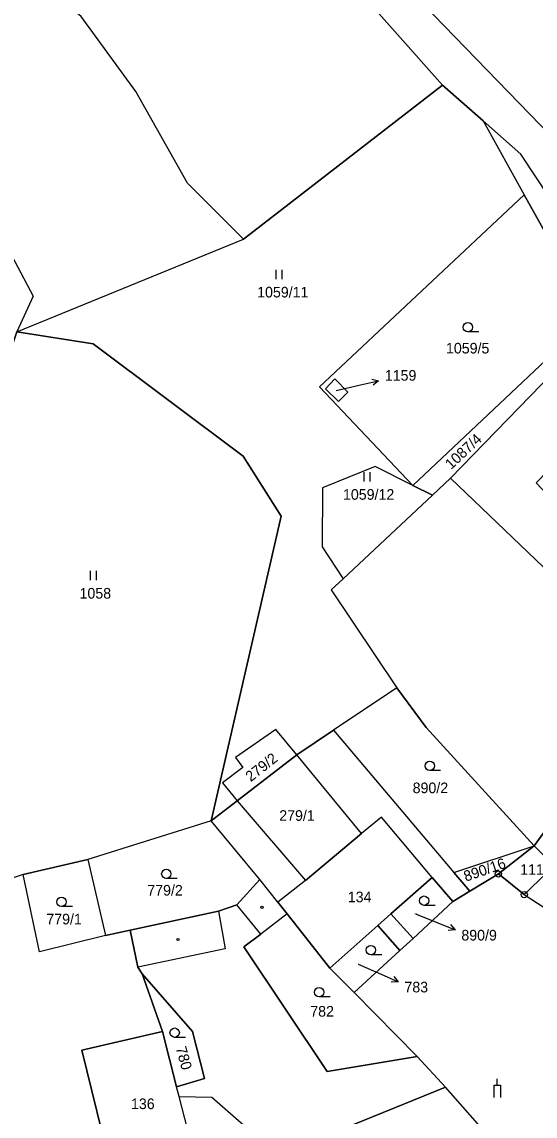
# Model space of a CAD drawing. Extents: x -654083 to -650132, y -1099819 to -1096699.
# Drawn here: x -653142.9 to -653060.7, y -1098197.5 to -1098022.1 of the extents above; entities that cross this region are included whole.
import ezdxf

# ---------------------------------------------------------------- set-up
doc = ezdxf.new("R2010")
doc.units = 0
for name, color, linetype in [('Geodetické body', 7, 'Continuous'), ('Hranice - vnitř_ kresba', 7, 'Continuous'), ('Obvody jako plochy', 7, 'Continuous'), ('Ostatní mapové značky 2', 7, 'Continuous'), ('Parcelní čísla', 7, 'Continuous'), ('Prvky pro prodl_ par_ č_', 7, 'Continuous'), ('Značky kultur', 7, 'Continuous'), ('Značky na budově ne v SPI', 7, 'Continuous')]:
    doc.layers.add(name, color=color, linetype=linetype)

msp = doc.modelspace()

# ---------------------------------------------------------------- linework, layer by layer
at = {"layer": 'Geodetické body'}
for centre, radius in [((-653066.55, -1098158.69), 0.5), ((-653066.55, -1098158.69), 0.001), ((-653062.42, -1098161.99), 0.5), ((-653062.42, -1098161.99), 0.001)]:
    msp.add_circle(centre, radius, dxfattribs=at)
at = {"layer": 'Hranice - vnitř_ kresba'}
for p, q in [((-653085.29, -1098149.58), (-653088.46, -1098152.23)), ((-653077.16, -1098159.23), (-653085.29, -1098149.58)), ((-653101.87, -1098163.22), (-653104.75, -1098159.59)), ((-653097.48, -1098159.75), (-653101.87, -1098163.22)), ((-653100.38, -1098165.1), (-653101.87, -1098163.22)), ((-653111.39, -1098164.65), (-653110.33, -1098170.7)), ((-653085.86, -1098166.94), (-653083.77, -1098165.07)), ((-653110.33, -1098170.7), (-653124.29, -1098173.63)), ((-653117.7, -1098194.34), (-653118.1, -1098192.78))]:
    msp.add_line(p, q, dxfattribs=at)
at = {"layer": 'Obvody jako plochy'}
for points in [[(-653150.23, -1097911.49), (-653071.26, -1097984.33), (-653053.39, -1098005.53), (-653037.15, -1098027.99), (-653053.78, -1098046.95), (-653058.1, -1098040.43), (-653190.24, -1097904.12), (-653233.05, -1097864.49), (-653269.43, -1097824.84), (-653263.01, -1097791.35), (-653215.43, -1097850.17)], [(-653159.78, -1097992.82), (-653143.05, -1097977.01), (-653174.94, -1097944.83), (-653220.04, -1097975.33), (-653208.83, -1097985.73), (-653199.6, -1098001.2), (-653194.63, -1098009.53), (-653169.63, -1098032.13), (-653152.81, -1098047.34), (-653149.48, -1098050.35), (-653141.08, -1098066.12), (-653143.72, -1098071.82), (-653107.4, -1098056.94), (-653116.37, -1098047.99), (-653124.61, -1098033.31), (-653133.37, -1098021.26), (-653147.28, -1098010.02)], [(-653075.5, -1098032.29), (-653107.4, -1098056.94), (-653116.37, -1098047.99), (-653124.61, -1098033.31), (-653133.37, -1098021.26), (-653147.28, -1098010.02), (-653159.78, -1097992.82), (-653143.05, -1097977.01), (-653139.93, -1097974.11), (-653120.37, -1097998.7), (-653111.98, -1097991.16)], [(-653062.45, -1098049.88), (-653095.19, -1098080.64), (-653080.27, -1098096.44), (-653086.3, -1098093.39), (-653094.72, -1098096.79), (-653094.8, -1098106.24), (-653091.4, -1098111.38), (-653093.32, -1098113.17), (-653082.85, -1098128.85), (-653092.97, -1098135.64), (-653098.84, -1098139.62), (-653102.23, -1098135.55), (-653108.65, -1098140.04), (-653107.47, -1098141.62), (-653110.73, -1098144.07), (-653108.39, -1098146.98), (-653112.54, -1098150.18), (-653101.36, -1098101.34), (-653107.45, -1098091.76), (-653131.48, -1098073.76), (-653143.72, -1098071.82), (-653107.4, -1098056.94), (-653075.5, -1098032.29), (-653069, -1098038.01)], [(-653052.35, -1098072.7), (-653049.59, -1098069.85), (-653056.05, -1098053.74), (-653062.97, -1098043.33), (-653069, -1098038.01), (-653062.45, -1098049.88), (-653051.51, -1098069.36), (-653080.27, -1098096.44), (-653077.11, -1098098), (-653074.21, -1098095.28)], [(-653153.06, -1098099.55), (-653163, -1098138.19), (-653175.95, -1098136.58), (-653183.53, -1098124.46), (-653202.43, -1098112.89), (-653152.81, -1098047.34), (-653149.48, -1098050.35), (-653141.08, -1098066.12), (-653143.72, -1098071.82)], [(-653080.27, -1098096.44), (-653051.51, -1098069.36), (-653062.45, -1098049.88), (-653095.19, -1098080.64)], [(-653037.53, -1098097.49), (-653052.73, -1098111.83), (-653053.71, -1098110.99), (-653055.61, -1098113.11), (-653074.21, -1098095.28), (-653052.35, -1098072.7), (-653049.59, -1098069.85), (-653045.09, -1098080.16)], [(-653143.72, -1098071.82), (-653131.48, -1098073.76), (-653107.45, -1098091.76), (-653101.36, -1098101.34), (-653112.54, -1098150.18), (-653132.3, -1098156.38), (-653142.69, -1098158.75), (-653160.81, -1098164.87), (-653163, -1098138.19), (-653153.06, -1098099.55)], [(-653055.61, -1098113.11), (-653074.21, -1098095.28), (-653052.35, -1098072.7), (-653045.09, -1098080.16), (-653060.52, -1098096), (-653050.13, -1098107.02), (-653053.71, -1098110.99)], [(-653090.65, -1098081.46), (-653092.19, -1098082.97), (-653094.27, -1098080.92), (-653092.76, -1098079.32)], [(-653092.76, -1098079.32), (-653090.65, -1098081.46), (-653092.19, -1098082.97), (-653094.27, -1098080.92)], [(-653091.4, -1098111.38), (-653077.11, -1098098), (-653080.27, -1098096.44), (-653086.3, -1098093.39), (-653094.72, -1098096.79), (-653094.8, -1098106.24)], [(-653053.71, -1098110.99), (-653055.61, -1098113.11), (-653074.21, -1098095.28), (-653077.11, -1098098), (-653091.4, -1098111.38), (-653093.32, -1098113.17), (-653082.85, -1098128.85), (-653078.13, -1098135.23), (-653060.83, -1098154.16), (-653049.44, -1098138.5), (-653045.05, -1098140.86), (-653035.15, -1098125.51), (-653030.07, -1098117.11), (-653027.32, -1098113), (-653031.29, -1098104.31), (-653037.53, -1098097.49), (-653052.73, -1098111.83)], [(-653060.83, -1098154.16), (-653078.13, -1098135.23), (-653082.85, -1098128.85), (-653092.97, -1098135.64), (-653073.71, -1098158.44)], [(-653080.21, -1098169.03), (-653082.36, -1098170.94), (-653085.86, -1098166.94), (-653093.57, -1098173.76), (-653100.38, -1098165.1), (-653104.62, -1098168.32), (-653108.47, -1098163.66), (-653104.75, -1098159.59), (-653112.54, -1098150.18), (-653108.39, -1098146.98), (-653097.48, -1098159.75), (-653088.46, -1098152.23), (-653098.84, -1098139.62), (-653092.97, -1098135.64), (-653073.71, -1098158.44), (-653071.14, -1098161.44), (-653073.84, -1098163.12), (-653077.16, -1098159.23), (-653083.77, -1098165.07)], [(-653098.84, -1098139.62), (-653102.23, -1098135.55), (-653108.65, -1098140.04), (-653107.47, -1098141.62), (-653110.73, -1098144.07), (-653108.39, -1098146.98)], [(-653108.65, -1098140.04), (-653107.47, -1098141.62), (-653110.73, -1098144.07), (-653108.39, -1098146.98), (-653098.84, -1098139.62), (-653102.23, -1098135.55)], [(-653097.48, -1098159.75), (-653088.46, -1098152.23), (-653098.84, -1098139.62), (-653108.39, -1098146.98)], [(-653108.39, -1098146.98), (-653097.48, -1098159.75), (-653088.46, -1098152.23), (-653098.84, -1098139.62)], [(-653053.99, -1098157.86), (-653052.76, -1098155.51), (-653045.05, -1098140.86), (-653049.44, -1098138.5), (-653060.83, -1098154.16), (-653057.61, -1098157.36), (-653055.14, -1098159.81)], [(-653085.86, -1098166.94), (-653083.77, -1098165.07), (-653077.16, -1098159.23), (-653085.29, -1098149.58), (-653088.46, -1098152.23), (-653097.48, -1098159.75), (-653101.87, -1098163.22), (-653100.38, -1098165.1), (-653093.57, -1098173.76)], [(-653108.47, -1098163.66), (-653104.75, -1098159.59), (-653112.54, -1098150.18), (-653132.3, -1098156.38), (-653129.48, -1098168.54), (-653125.55, -1098167.69), (-653111.39, -1098164.65)], [(-653066.55, -1098158.69), (-653071.14, -1098161.44), (-653073.71, -1098158.44), (-653060.83, -1098154.16)], [(-653062.42, -1098161.99), (-653066.55, -1098158.69), (-653060.83, -1098154.16), (-653057.61, -1098157.36)], [(-653132.3, -1098156.38), (-653129.48, -1098168.54), (-653140.06, -1098171.16), (-653142.69, -1098158.75)], [(-653140.06, -1098171.16), (-653142.69, -1098158.75), (-653160.81, -1098164.87), (-653165.45, -1098167.24), (-653166.29, -1098184.39), (-653163.28, -1098198.26), (-653156.38, -1098205.89), (-653150.52, -1098224.84), (-653141.18, -1098219.21), (-653127.65, -1098213.56), (-653113.09, -1098212.74), (-653113.57, -1098209.43), (-653115.41, -1098203.29), (-653128.45, -1098206.67), (-653133.29, -1098186.91), (-653120.36, -1098183.92), (-653123.61, -1098174.68), (-653124.29, -1098173.63), (-653125.55, -1098167.69), (-653129.48, -1098168.54)], [(-653055.14, -1098159.81), (-653057.61, -1098157.36), (-653062.42, -1098161.99), (-653051.6, -1098169.04), (-653046.15, -1098163.95), (-653053.32, -1098158.38), (-653053.99, -1098157.86)], [(-653073.84, -1098163.12), (-653080.21, -1098169.03), (-653083.77, -1098165.07), (-653077.16, -1098159.23)], [(-653079.59, -1098187.95), (-653094, -1098190.37), (-653107.31, -1098170.36), (-653104.62, -1098168.32), (-653108.47, -1098163.66), (-653111.39, -1098164.65), (-653125.55, -1098167.69), (-653124.29, -1098173.63), (-653123.61, -1098174.68), (-653115.58, -1098183.94), (-653113.62, -1098191.47), (-653118.1, -1098192.78), (-653120.36, -1098183.92), (-653133.29, -1098186.91), (-653128.45, -1098206.67), (-653115.41, -1098203.29), (-653117.7, -1098194.34), (-653112.47, -1098194.44), (-653101.85, -1098203.76), (-653075.01, -1098192.86)], [(-653093.57, -1098173.76), (-653100.38, -1098165.1), (-653104.62, -1098168.32), (-653107.31, -1098170.36), (-653094, -1098190.37), (-653079.59, -1098187.95), (-653089.68, -1098177.7)], [(-653082.36, -1098170.94), (-653089.68, -1098177.7), (-653093.57, -1098173.76), (-653085.86, -1098166.94)], [(-653115.58, -1098183.94), (-653123.61, -1098174.68), (-653120.36, -1098183.92), (-653118.1, -1098192.78), (-653113.62, -1098191.47)], [(-653128.45, -1098206.67), (-653115.41, -1098203.29), (-653117.7, -1098194.34), (-653118.1, -1098192.78), (-653120.36, -1098183.92), (-653133.29, -1098186.91)], [(-653054.02, -1098216.68), (-653075.01, -1098192.86), (-653101.85, -1098203.76), (-653113.57, -1098209.43), (-653113.09, -1098212.74), (-653105.4, -1098235.64), (-653102.24, -1098235.17), (-653085.2, -1098247.42), (-653065.64, -1098241.83)], [(-653101.85, -1098203.76), (-653113.57, -1098209.43), (-653115.41, -1098203.29), (-653117.7, -1098194.34), (-653112.47, -1098194.44)]]:
    msp.add_lwpolyline(points, close=True, dxfattribs=at)
for points in [[(-653190.24, -1097904.12), (-653058.1, -1098040.43), (-653053.78, -1098046.95), (-653049.22, -1098053.83), (-653045.67, -1098067.27), (-653044.29, -1098069.82), (-653034.66, -1098087.65), (-653023.18, -1098108.58), (-653022.38, -1098110.19), (-653027.32, -1098113), (-653031.29, -1098104.31), (-653037.53, -1098097.49), (-653045.09, -1098080.16), (-653049.59, -1098069.85), (-653056.05, -1098053.74), (-653062.97, -1098043.33), (-653069, -1098038.01), (-653075.5, -1098032.29), (-653111.98, -1097991.16), (-653194.36, -1097906.79)], [(-653054.02, -1098216.68), (-653075.01, -1098192.86), (-653079.59, -1098187.95), (-653089.68, -1098177.7), (-653082.36, -1098170.94), (-653080.21, -1098169.03), (-653073.84, -1098163.12), (-653071.14, -1098161.44), (-653066.55, -1098158.69), (-653062.42, -1098161.99), (-653051.6, -1098169.04)]]:
    msp.add_lwpolyline(points, dxfattribs=at)
at = {"layer": 'Ostatní mapové značky 2'}
msp.add_line((-653066.74, -1098192.52), (-653066.74, -1098191.52), dxfattribs=at)
msp.add_lwpolyline([(-653067.24, -1098194.52), (-653067.24, -1098192.52), (-653066.24, -1098192.52), (-653066.24, -1098194.52)], dxfattribs=at)
at = {"layer": 'Prvky pro prodl_ par_ č_'}
for p, q in [((-653088.67, -1098080.32), (-653085.75, -1098079.64)), ((-653092.53, -1098081.23), (-653088.67, -1098080.32)), ((-653079.84, -1098165.07), (-653076.27, -1098166.52)), ((-653076.27, -1098166.52), (-653073.49, -1098167.65)), ((-653089.01, -1098173.14), (-653085.35, -1098174.76)), ((-653085.35, -1098174.76), (-653082.61, -1098175.97))]:
    msp.add_line(p, q, dxfattribs=at)
for points in [[(-653086.84, -1098079.38), (-653085.75, -1098079.64), (-653086.61, -1098080.35)], [(-653074.23, -1098166.81), (-653073.49, -1098167.65), (-653074.61, -1098167.74)], [(-653083.32, -1098175.11), (-653082.61, -1098175.97), (-653083.72, -1098176.03)]]:
    msp.add_lwpolyline(points, dxfattribs=at)
at = {"layer": 'Značky kultur'}
for p, q in [((-653102.23, -1098061.86), (-653102.23, -1098063.36)), ((-653101.2, -1098063.36), (-653101.2, -1098061.86)), ((-653069.68, -1098071.82), (-653071.43, -1098071.82)), ((-653088.11, -1098094.28), (-653088.11, -1098095.78)), ((-653087.08, -1098095.78), (-653087.08, -1098094.28)), ((-653131.96, -1098110.12), (-653131.96, -1098111.62)), ((-653130.94, -1098111.62), (-653130.94, -1098110.12)), ((-653075.81, -1098142.11), (-653077.56, -1098142.11)), ((-653118, -1098159.44), (-653119.75, -1098159.44)), ((-653134.8, -1098163.92), (-653136.55, -1098163.92)), ((-653076.7, -1098163.72), (-653078.45, -1098163.72)), ((-653085.22, -1098171.64), (-653086.97, -1098171.64)), ((-653093.52, -1098178.39), (-653095.27, -1098178.39)), ((-653116.66, -1098184.87), (-653118.41, -1098184.87))]:
    msp.add_line(p, q, dxfattribs=at)
for centre in [(-653071.43, -1098071.07), (-653077.56, -1098141.36), (-653119.75, -1098158.69), (-653136.55, -1098163.17), (-653078.45, -1098162.97), (-653086.97, -1098170.89), (-653095.27, -1098177.64), (-653118.41, -1098184.12)]:
    msp.add_circle(centre, 0.75, dxfattribs=at)
at = {"layer": 'Značky na budově ne v SPI'}
for centre in [(-653104.41, -1098164.04), (-653117.87, -1098169.2)]:
    msp.add_circle(centre, 0.175, dxfattribs=at)

# ---------------------------------------------------------------- texts
at = {"layer": 'Parcelní čísla'}
for s, height, p in [('1059/11', 1.7, (-653105.2, -1098066.3)), ('1059/5', 1.7, (-653074.95, -1098075.28)), ('1159', 0.1, (-653092.63, -1098081.23)), ('1059/12', 1.7, (-653091.45, -1098098.72)), ('1058', 1.7, (-653133.65, -1098114.56)), ('890/2', 1.7, (-653080.29, -1098145.74)), ('279/1', 1.7, (-653101.66, -1098150.17)), ('1117', 1.7, (-653063.06, -1098158.82)), ('779/2', 1.7, (-653122.8, -1098162.15)), ('134', 1.7, (-653090.68, -1098163.22)), ('779/1', 1.7, (-653138.97, -1098166.77)), ('890/9', 0.1, (-653080.02, -1098165.07)), ('783', 0.1, (-653089.12, -1098173.14)), ('782', 1.7, (-653096.69, -1098181.55)), ('136', 1.7, (-653125.41, -1098196.37))]:
    msp.add_text(s, height=height, dxfattribs=at).set_placement(p)
for s, rotation, p in [('1087/4', 43.146, (-653074.13, -1098093.96)), ('279/2', 38.268, (-653106.23, -1098144)), ('890/16', 19.071, (-653071.77, -1098159.94)), ('780', 285.669, (-653118.26, -1098186.59))]:
    msp.add_text(s, height=1.7, rotation=rotation, dxfattribs=at).set_placement(p)
at = {"layer": 'Prvky pro prodl_ par_ č_'}
for s, p in [('1159', (-653084.75, -1098079.64)), ('890/9', (-653072.49, -1098169.35)), ('783', (-653081.61, -1098177.67))]:
    msp.add_text(s, height=1.7, dxfattribs=at).set_placement(p)

doc.saveas('drawing.dxf')
